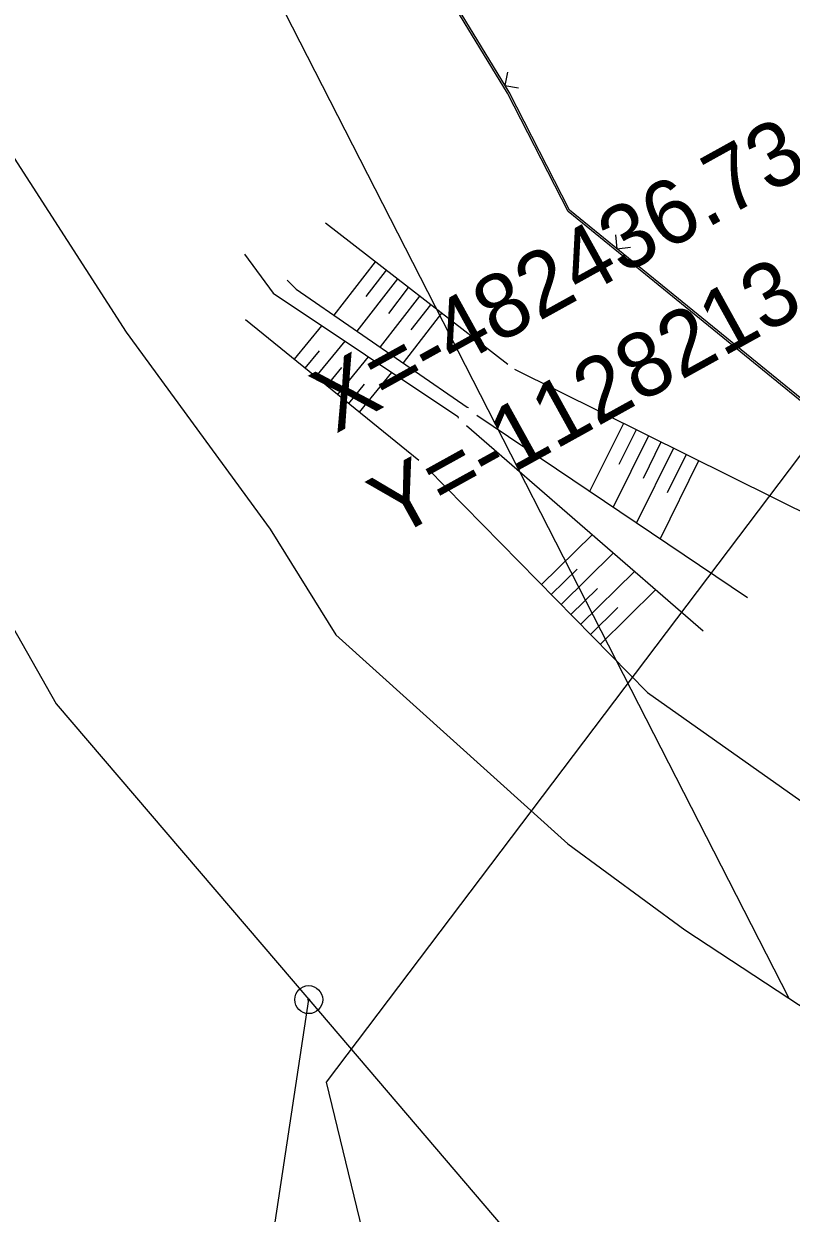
# Model space of a CAD drawing. Extents: x -483721 to -481876, y -1129170 to -1127366.
# Drawn here: x -482470.55 to -482443.12, y -1128247 to -1128204.5 of the extents above; entities that cross this region are included whole.
import ezdxf

# ---------------------------------------------------------------- set-up
doc = ezdxf.new("R2010")
doc.units = 0
for name, color, linetype in [('Hranice parcel', 7, 'Continuous'), ('u_OP_lesa', 7, 'Continuous'), ('u_vytyčení', 7, 'Continuous'), ('Značky bodu BP', 7, 'Continuous'), ('ˇ12', 7, 'Continuous'), ('ˇ8', 7, 'Continuous')]:
    doc.layers.add(name, color=color, linetype=linetype)

msp = doc.modelspace()

# ---------------------------------------------------------------- linework, layer by layer
at = {"layer": 'Hranice parcel'}
for p, q in [((-482475.8, -1128175.59), (-482443.21, -1128239.32)), ((-482486.64, -1128198.4), (-482469.4, -1128228.8)), ((-482469.4, -1128228.8), (-482460.37, -1128239.37)), ((-482446.93, -1128236.88), (-482443.21, -1128239.32)), ((-482463, -1128256.76), (-482460.37, -1128239.37)), ((-482460.37, -1128239.37), (-482452.95, -1128248.05)), ((-482443.21, -1128239.32), (-482430.5, -1128247.66))]:
    msp.add_line(p, q, dxfattribs=at)
for points in [[(-482378.58, -1128267.55), (-482422.4, -1128234.54), (-482424.97, -1128232.6), (-482436.98, -1128222.89), (-482441.06, -1128219.38), (-482451.1, -1128211.21), (-482453.27, -1128206.98), (-482457.35, -1128200.28), (-482472.77, -1128174.94)], [(-482487.52, -1128178.13), (-482490.56, -1128178.78), (-482466.89, -1128215.52), (-482461.75, -1128222.56), (-482459.4, -1128226.34), (-482451.11, -1128233.8), (-482446.93, -1128236.88)]]:
    msp.add_lwpolyline(points, dxfattribs=at)
at = {"layer": 'u_OP_lesa'}
msp.add_lwpolyline([(-482417.647, -1128382.401), (-482432.277, -1128336.352), (-482451.921, -1128274.508), (-482459.735, -1128242.317), (-482439.858, -1128216.048), (-482430.661, -1128194.677), (-482468.003, -1128132.413)], dxfattribs=at)
at = {"layer": 'Značky bodu BP'}
for radius in [0.5, 0.0303]:
    msp.add_circle((-482460.37, -1128239.37), radius, dxfattribs=at)
at = {"layer": 'ˇ12'}
for p, q in [((-482453.25, -1128216.68), (-482459.77, -1128211.63)), ((-482462.66, -1128212.73), (-482461.64, -1128214.13)), ((-482457.99, -1128213.01), (-482459.47, -1128214.91)), ((-482457.6, -1128213.31), (-482458.33, -1128214.25)), ((-482461.14, -1128213.66), (-482460.82, -1128213.98)), ((-482457.2, -1128213.62), (-482458.65, -1128215.48)), ((-482461.64, -1128214.13), (-482455.04, -1128218.54)), ((-482460.82, -1128213.98), (-482454.71, -1128218.2)), ((-482456.41, -1128214.23), (-482457.82, -1128216.05)), ((-482456.81, -1128213.93), (-482457.52, -1128214.85)), ((-482456.02, -1128214.54), (-482456.72, -1128215.44)), ((-482456.43, -1128220.11), (-482462.63, -1128215.08)), ((-482455.62, -1128214.84), (-482457, -1128216.62)), ((-482460.88, -1128216.49), (-482459.9, -1128215.29)), ((-482460.11, -1128217.12), (-482459.07, -1128215.84)), ((-482460.5, -1128216.81), (-482459.99, -1128216.19)), ((-482459.33, -1128217.75), (-482458.23, -1128216.4)), ((-482459.72, -1128217.44), (-482459.19, -1128216.78)), ((-482441.91, -1128222.36), (-482453, -1128216.86)), ((-482458.55, -1128218.38), (-482457.4, -1128216.96)), ((-482458.94, -1128218.07), (-482458.38, -1128217.38)), ((-482455.04, -1128218.54), (-482455.03, -1128218.59)), ((-482454.71, -1128218.2), (-482454.66, -1128218.21)), ((-482454.36, -1128218.49), (-482444.69, -1128225)), ((-482446.27, -1128226.2), (-482454.73, -1128218.87)), ((-482449.12, -1128218.78), (-482450.33, -1128221.21)), ((-482448.23, -1128219.23), (-482449.49, -1128221.77)), ((-482448.67, -1128219.01), (-482449.29, -1128220.25)), ((-482447.33, -1128219.67), (-482448.65, -1128222.33)), ((-482447.78, -1128219.45), (-482448.42, -1128220.75)), ((-482446.44, -1128220.12), (-482447.81, -1128222.9)), ((-482446.88, -1128219.89), (-482447.56, -1128221.26)), ((-482456.13, -1128220.39), (-482448.26, -1128228.4)), ((-482452.05, -1128224.54), (-482450.24, -1128222.76)), ((-482451.35, -1128225.25), (-482449.49, -1128223.42)), ((-482451.7, -1128224.9), (-482450.78, -1128223.99)), ((-482450.65, -1128225.96), (-482448.73, -1128224.07)), ((-482451, -1128225.61), (-482450.05, -1128224.68)), ((-482449.95, -1128226.68), (-482447.97, -1128224.73)), ((-482450.3, -1128226.32), (-482449.32, -1128225.36)), ((-482448.26, -1128228.4), (-482437.18, -1128236.22))]:
    msp.add_line(p, q, dxfattribs=at)
at = {"layer": 'ˇ8'}
for p, q in [((-482453.27, -1128206.226), (-482453.356, -1128206.711)), ((-482453.356, -1128206.711), (-482452.871, -1128206.797)), ((-482449.406, -1128212.049), (-482449.356, -1128212.539)), ((-482449.356, -1128212.539), (-482448.866, -1128212.489))]:
    msp.add_line(p, q, dxfattribs=at)
msp.add_lwpolyline([(-482433.73, -1128225.42), (-482441.015, -1128219.326), (-482451.044, -1128211.165), (-482453.209, -1128206.946), (-482457.29, -1128200.244), (-482473.401, -1128173.718), (-482468.043, -1128170.503), (-482462.036, -1128177.456)], dxfattribs=at)

# ---------------------------------------------------------------- texts
at = {"layer": 'u_vytyčení'}
for s, p in [('X=-482436.7340', (-482459.406, -1128219.158)), ('Y=-1128213.6512', (-482457.324, -1128222.92))]:
    msp.add_text(s, height=2.3, rotation=28.9559, dxfattribs=at).set_placement(p)

doc.saveas('drawing.dxf')
